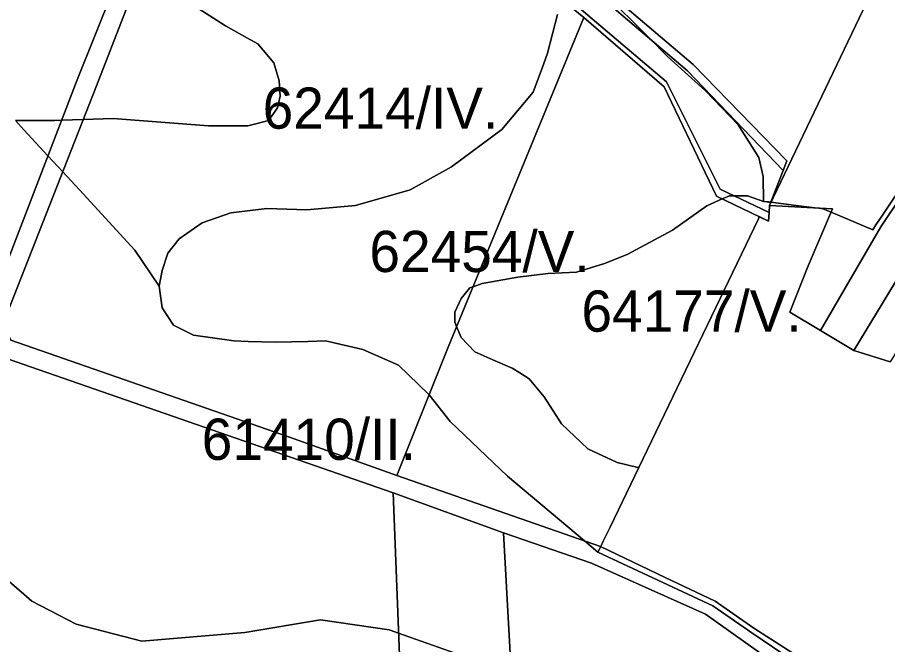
# Model space of a CAD drawing. Extents: x -522079 to -518792, y -1142400 to -1139961.
# Drawn here: x -520002.4 to -519685.2, y -1141371.1 to -1141142.6 of the extents above; entities that cross this region are included whole.
import ezdxf

# ---------------------------------------------------------------- set-up
doc = ezdxf.new("R2010")
doc.units = 0
for name, color, linetype in [('Hranice parcel', 7, 'Continuous'), ('Parcelní čísla', 7, 'Continuous'), ('Poz předměty', 7, 'Continuous'), ('Značky bodu BP', 7, 'Continuous'), ('Značky budov', 7, 'Continuous')]:
    doc.layers.add(name, color=color, linetype=linetype)

msp = doc.modelspace()

# ---------------------------------------------------------------- linework, layer by layer
at = {"layer": 'Hranice parcel'}
msp.add_lwpolyline([(-519980.55, -1141165.39), (-519948.1, -1141084.44), (-519944.08, -1141074.41), (-519938.17, -1141076.59), (-519941.9, -1141085.78), (-519973.57, -1141167.53), (-520007.53, -1141254.06), (-520004.78, -1141260.17), (-520020.92, -1141254.2), (-520014.17, -1141252.24)], close=True, dxfattribs=at)
for points in [[(-520004.78, -1141260.17), (-519903.26, -1141295.46), (-519864.09, -1141309.46), (-519789.84, -1141335.36), (-519766.26, -1141346.58), (-519748.09, -1141355.2), (-519733.94, -1141365.09), (-519705.92, -1141383)], [(-519727.64, -1141376.95), (-519751.63, -1141360.04), (-519793.08, -1141341.43), (-519825.24, -1141330.38), (-519865.42, -1141315.8), (-520005.98, -1141266.96)]]:
    msp.add_lwpolyline(points, dxfattribs=at)
at = {"layer": 'Parcelní čísla'}
for points in [[(-520079.53, -1141019.58), (-520032.33, -1141047.7), (-519951.21, -1141077.01), (-519948.1, -1141084.44), (-519980.55, -1141165.39), (-520014.17, -1141252.24), (-520020.92, -1141254.2), (-520158.56, -1141206.98), (-520129.38, -1141144.09)], [(-519935.26, -1141083.16), (-519941.9, -1141085.78), (-519938.17, -1141076.59), (-519933.25, -1141078.41), (-519920.33, -1141083.18), (-519905.71, -1141088.58), (-519900.64, -1141090.45), (-519884.82, -1141099.57), (-519851.93, -1141096.73), (-519839.81, -1141095.68), (-519827.19, -1141099.4), (-519800.19, -1141122.28), (-519756.03, -1141159.77), (-519721.93, -1141194.85), (-519723.28, -1141198.33), (-519758.08, -1141162.05), (-519828.65, -1141102.04), (-519840, -1141098.37), (-519884.97, -1141102.71), (-519902.89, -1141094.84)], [(-519864.09, -1141309.46), (-519903.26, -1141295.46), (-520004.78, -1141260.17), (-520007.53, -1141254.06), (-519973.57, -1141167.53), (-519941.9, -1141085.78), (-519935.26, -1141083.16), (-519903.85, -1141097.73), (-519880.39, -1141112.19), (-519838.58, -1141107.96), (-519795.94, -1141142.67), (-519845.38, -1141262.74)], [(-519935.26, -1141083.16), (-519902.89, -1141094.84), (-519879.3, -1141109.16), (-519838.27, -1141104.49), (-519765.82, -1141166.07), (-519746.23, -1141205.14), (-519728.39, -1141213.65), (-519728.58, -1141216.84), (-519747.5, -1141207.73), (-519766.69, -1141167.92), (-519795.94, -1141142.67), (-519838.58, -1141107.96), (-519880.39, -1141112.19), (-519903.85, -1141097.73)], [(-519728.23, -1141211.06), (-519728.39, -1141213.65), (-519746.23, -1141205.14), (-519765.82, -1141166.07), (-519838.27, -1141104.49), (-519879.3, -1141109.16), (-519902.89, -1141094.84), (-519884.97, -1141102.71), (-519840, -1141098.37), (-519828.65, -1141102.04), (-519758.08, -1141162.05), (-519723.28, -1141198.33)], [(-519988.83, -1141621.62), (-519993.67, -1141617.6), (-520005.29, -1141383.92), (-520010.89, -1141271.2), (-520005.98, -1141266.96), (-519865.42, -1141315.8), (-519860.18, -1141449.65), (-519851.95, -1141597.5), (-519865.85, -1141595.23), (-519871.86, -1141594.87), (-519890.16, -1141599.67)], [(-519865.42, -1141315.8), (-519825.24, -1141330.38), (-519817.29, -1141473.31), (-519808.88, -1141634.44), (-519812.26, -1141630.88), (-519831.57, -1141610.83), (-519850.96, -1141597.66), (-519851.95, -1141597.5), (-519860.18, -1141449.65)], [(-519825.24, -1141330.38), (-519793.08, -1141341.43), (-519751.63, -1141360.04), (-519727.64, -1141376.95), (-519718.52, -1141529.55), (-519710.49, -1141703.04), (-519778.21, -1141665.51), (-519784.86, -1141659.77), (-519808.88, -1141634.44), (-519817.29, -1141473.31)]]:
    msp.add_lwpolyline(points, close=True, dxfattribs=at)
at = {"layer": 'Poz předměty'}
msp.add_lwpolyline([(-519746.51, -1141048.43), (-519749.67, -1141057.47), (-519744.08, -1141063.56), (-519732.93, -1141063.24), (-519729.51, -1141072.8), (-519719.95, -1141075.61), (-519692.8, -1141119.72), (-519691.83, -1141116.63), (-519686.19, -1141123.12), (-519688.75, -1141128.51), (-519728.23, -1141211.06), (-519723.28, -1141198.33), (-519721.93, -1141194.85), (-519756.03, -1141159.77), (-519800.19, -1141122.28), (-519766.87, -1141035.85)], close=True, dxfattribs=at)
at = {"layer": 'Značky bodu BP'}
for points in [[(-519788.91, -1141133.25), (-519772.01, -1141150.2), (-519765.41, -1141156.82), (-519751.62, -1141169.38), (-519739.72, -1141181.79), (-519732.14, -1141193.58), (-519730.59, -1141200.57), (-519730.38, -1141209.61), (-519736.26, -1141207.57), (-519740.38, -1141207.57), (-519741.13, -1141207.57), (-519742.85, -1141207.57), (-519743.69, -1141207.94), (-519745.44, -1141208.72), (-519751.04, -1141211.22), (-519763.55, -1141220.12), (-519780.16, -1141229.02), (-519788.35, -1141232.21), (-519798.59, -1141235.41), (-519809.05, -1141235.87), (-519819.97, -1141237.24), (-519832.94, -1141239.52), (-519836.31, -1141240.7), (-519837.49, -1141241.11), (-519840.67, -1141245), (-519842.95, -1141250.01), (-519842.95, -1141253.67), (-519842.29, -1141255.24), (-519840.67, -1141259.14), (-519835.67, -1141264.39), (-519829.07, -1141267.36), (-519822.02, -1141270.33), (-519819.3, -1141272.04), (-519815.87, -1141274.2), (-519810.42, -1141280.82), (-519804.05, -1141290.63), (-519794.49, -1141299.76), (-519783.8, -1141304.78), (-519776.68, -1141306.41), (-519775.91, -1141306.58), (-519777.36, -1141309.59), (-519786.36, -1141328.27), (-519788.83, -1141333.41), (-519789.78, -1141335.38), (-519790.77, -1141337.44), (-519795.65, -1141333.33), (-519823.76, -1141309.68), (-519844.65, -1141289.76), (-519852.31, -1141280.04), (-519852.49, -1141279.81), (-519863.46, -1141269.33), (-519876.52, -1141263.57), (-519890.1, -1141260.42), (-519896.48, -1141260.6), (-519908.38, -1141260.95), (-519918.25, -1141260.6), (-519923.52, -1141260.42), (-519938.15, -1141258.33), (-519945.46, -1141254.66), (-519949.64, -1141248.37), (-519950.69, -1141240.51), (-519949.64, -1141234.75), (-519947.55, -1141228.46), (-519943.37, -1141223.22), (-519935.02, -1141217.46), (-519924.64, -1141213.82), (-519924.57, -1141213.79), (-519911.51, -1141212.22), (-519896.89, -1141212.74), (-519879.13, -1141211.17), (-519859.28, -1141205.41), (-519844.13, -1141197.02), (-519825.85, -1141183.4), (-519814.36, -1141169.77), (-519812.81, -1141165.59), (-519811.15, -1141161.1), (-519809.14, -1141155.63), (-519805.48, -1141141.48)], [(-519658.25, -1141171.6), (-519687.52, -1141215.32), (-519689.44, -1141218.2), (-519690.63, -1141219.98), (-519705.81, -1141213.57), (-519708.77, -1141212.32), (-519710.26, -1141212.13), (-519711.69, -1141211.95), (-519718.47, -1141211.1), (-519727.7, -1141209.95), (-519727.78, -1141209.93), (-519728.46, -1141209.85), (-519728.55, -1141209.84), (-519729.22, -1141209.76), (-519730.38, -1141209.61), (-519730.59, -1141200.57), (-519732.14, -1141193.58), (-519739.72, -1141181.79), (-519751.62, -1141169.38), (-519765.41, -1141156.82), (-519772.01, -1141150.2), (-519788.91, -1141133.25)], [(-519938.01, -1141138.42), (-519926.55, -1141145.64), (-519918.49, -1141150.13), (-519914.77, -1141152.2), (-519908.88, -1141159.1), (-519906.92, -1141165.66), (-519906.59, -1141171.24), (-519907.57, -1141175.51), (-519909.08, -1141177.63), (-519910.85, -1141180.1), (-519915.05, -1141181.21), (-519918.37, -1141182.08), (-519932.77, -1141182.08), (-519967.46, -1141179.45), (-519978.38, -1141179.78), (-519986.22, -1141180.03), (-519988.72, -1141180.1), (-520000, -1141180.1), (-520003.12, -1141180.1)], [(-519805.48, -1141141.48), (-519809.14, -1141155.63), (-519811.15, -1141161.1), (-519812.81, -1141165.59), (-519814.36, -1141169.77), (-519825.85, -1141183.4), (-519844.13, -1141197.02), (-519859.28, -1141205.41), (-519879.13, -1141211.17), (-519896.89, -1141212.74), (-519911.51, -1141212.22), (-519924.57, -1141213.79), (-519924.64, -1141213.82), (-519935.02, -1141217.46), (-519943.37, -1141223.22), (-519947.55, -1141228.46), (-519949.64, -1141234.75), (-519950.69, -1141240.51), (-519959.56, -1141227.41), (-519979.78, -1141205.46), (-519985.86, -1141198.85), (-519991.24, -1141193.01), (-520000, -1141183.5), (-520003.12, -1141180.1), (-520000, -1141180.1), (-519988.72, -1141180.1), (-519986.22, -1141180.03), (-519978.38, -1141179.78), (-519967.46, -1141179.45), (-519932.77, -1141182.08), (-519918.37, -1141182.08), (-519915.05, -1141181.21), (-519910.85, -1141180.1), (-519909.08, -1141177.63), (-519907.57, -1141175.51), (-519906.59, -1141171.24), (-519906.92, -1141165.66), (-519908.88, -1141159.1), (-519914.77, -1141152.2), (-519918.49, -1141150.13), (-519926.55, -1141145.64), (-519938.01, -1141138.42)], [(-519723.37, -1141374.45), (-519734.68, -1141366.82), (-519748.86, -1141356.99), (-519790.77, -1141337.44), (-519789.78, -1141335.38), (-519788.83, -1141333.41), (-519786.36, -1141328.27), (-519777.36, -1141309.59), (-519775.91, -1141306.58), (-519732.26, -1141215.97), (-519732.04, -1141215.17), (-519728.58, -1141216.84), (-519728.39, -1141213.65), (-519728.23, -1141211.06), (-519727.7, -1141209.95), (-519718.47, -1141211.1), (-519711.69, -1141211.95), (-519710.26, -1141212.13), (-519708.77, -1141212.32), (-519705.81, -1141213.57), (-519690.63, -1141219.98), (-519689.44, -1141218.2), (-519687.52, -1141215.32), (-519658.25, -1141171.6)], [(-520003.12, -1141180.1), (-520000, -1141183.5), (-519991.24, -1141193.01), (-519985.86, -1141198.85), (-519979.78, -1141205.46), (-519959.56, -1141227.41), (-519950.69, -1141240.51), (-519949.64, -1141248.37), (-519945.46, -1141254.66), (-519938.15, -1141258.33), (-519923.52, -1141260.42), (-519918.25, -1141260.6), (-519908.38, -1141260.95), (-519896.48, -1141260.6), (-519890.1, -1141260.42), (-519876.52, -1141263.57), (-519863.46, -1141269.33), (-519852.49, -1141279.81), (-519852.31, -1141280.04), (-519844.65, -1141289.76), (-519823.76, -1141309.68), (-519795.65, -1141333.33), (-519790.77, -1141337.44), (-519748.86, -1141356.99), (-519734.68, -1141366.82), (-519723.37, -1141374.45)], [(-519828.32, -1141379.25), (-519863.42, -1141366.88), (-519866.55, -1141365.77), (-519866.87, -1141365.66), (-519891.88, -1141362), (-519919.49, -1141366.7), (-519957.01, -1141369.84), (-519980.97, -1141363.57), (-519997.12, -1141355.21), (-520000, -1141352.72), (-520007.15, -1141346.54)], [(-520007.15, -1141346.54), (-520000, -1141352.72), (-519997.12, -1141355.21), (-519980.97, -1141363.57), (-519957.01, -1141369.84), (-519919.49, -1141366.7), (-519891.88, -1141362), (-519866.87, -1141365.66), (-519866.55, -1141365.77), (-519863.42, -1141366.88), (-519828.32, -1141379.25)]]:
    msp.add_lwpolyline(points, dxfattribs=at)
msp.add_lwpolyline([(-519730.38, -1141209.61), (-519729.22, -1141209.76), (-519728.55, -1141209.84), (-519728.46, -1141209.85), (-519727.78, -1141209.93), (-519727.7, -1141209.95), (-519728.23, -1141211.06), (-519728.39, -1141213.65), (-519728.58, -1141216.84), (-519732.04, -1141215.17), (-519732.26, -1141215.97), (-519775.91, -1141306.58), (-519776.68, -1141306.41), (-519783.8, -1141304.78), (-519794.49, -1141299.76), (-519804.05, -1141290.63), (-519810.42, -1141280.82), (-519815.87, -1141274.2), (-519819.3, -1141272.04), (-519822.02, -1141270.33), (-519829.07, -1141267.36), (-519835.67, -1141264.39), (-519840.67, -1141259.14), (-519842.29, -1141255.24), (-519842.95, -1141253.67), (-519842.95, -1141250.01), (-519840.67, -1141245), (-519837.49, -1141241.11), (-519836.31, -1141240.7), (-519832.94, -1141239.52), (-519819.97, -1141237.24), (-519809.05, -1141235.87), (-519798.59, -1141235.41), (-519788.35, -1141232.21), (-519780.16, -1141229.02), (-519763.55, -1141220.12), (-519751.04, -1141211.22), (-519745.44, -1141208.72), (-519743.69, -1141207.94), (-519742.85, -1141207.57), (-519741.13, -1141207.57), (-519740.38, -1141207.57), (-519736.26, -1141207.57)], close=True, dxfattribs=at)
at = {"layer": 'Značky budov'}
for points in [[(-519687.67, -1141218.86), (-519709.65, -1141256.63), (-519720.8, -1141249.93), (-519714.2, -1141233.06), (-519705.26, -1141212.3), (-519728.23, -1141211.06), (-519688.75, -1141128.51), (-519686.19, -1141123.12), (-519676.06, -1141134.77), (-519667.13, -1141153.28), (-519663.19, -1141164.28), (-519654.81, -1141169.94)], [(-519697.46, -1141263.95), (-519709.65, -1141256.63), (-519687.67, -1141218.86), (-519654.81, -1141169.94), (-519652.19, -1141178.57), (-519646.01, -1141182.51), (-519676.14, -1141228.74)], [(-519635, -1141188.59), (-519684.2, -1141268.01), (-519697.46, -1141263.95), (-519676.14, -1141228.74), (-519646.01, -1141182.51), (-519637.37, -1141188.02)]]:
    msp.add_lwpolyline(points, close=True, dxfattribs=at)
msp.add_lwpolyline([(-519705.92, -1141383), (-519733.94, -1141365.09), (-519748.09, -1141355.2), (-519766.26, -1141346.58), (-519789.84, -1141335.36), (-519864.09, -1141309.46), (-519845.38, -1141262.74), (-519795.94, -1141142.67), (-519766.69, -1141167.92), (-519747.5, -1141207.73), (-519728.58, -1141216.84), (-519728.39, -1141213.65), (-519728.23, -1141211.06), (-519705.26, -1141212.3), (-519714.2, -1141233.06), (-519720.8, -1141249.93), (-519709.65, -1141256.63), (-519697.46, -1141263.95), (-519684.2, -1141268.01)], dxfattribs=at)

# ---------------------------------------------------------------- texts
at = {"layer": 'Značky bodu BP'}
for s, rotation, p in [('62414/IV.', 0, (-519912.98, -1141183.14)), ('62454/V.', 360, (-519874.07, -1141235.35)), ('64177/V.', 0, (-519796.79, -1141257.07)), ('61410/II.', 360, (-519935.2, -1141303.77))]:
    msp.add_text(s, height=15, rotation=rotation, dxfattribs=at).set_placement(p)

doc.saveas('drawing.dxf')
